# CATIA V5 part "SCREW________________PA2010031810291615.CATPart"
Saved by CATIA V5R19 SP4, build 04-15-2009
Part number: SCREW________________PA2010031810291615
Bounding box of the stored display mesh (mm): x -2.742 to 2.742, y -2.75 to 2.75, z -16 to 2
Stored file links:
  E:\CadInnWork\1\SCREW________________PA2010031810291615.CATPart
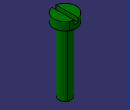
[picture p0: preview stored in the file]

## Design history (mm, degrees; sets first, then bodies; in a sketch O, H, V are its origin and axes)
Parameters
  Update = false
  PDM_version = "A"
  PDM_iteration = 1
  PDM_owner = "moren                    "
  PDM_comment = ""
  PDM_partnumber = "PA002170EA6A57201003181029160015"
Body1 (main body)
  Sketch1 on yz-plane, origin (0, 0, 0), H (0, 1, 0), V (0, 0, 1)
    axis line L1 (0, 73.7857) -> (0, -77.8237)
    point P1 (0, 73.7857)
    point P3 (0, 2)
    line L2 (0, 2) -> (2.75, 2)
    line L3 (2.75, 2) -> (2.75, 0)
    point P5 (2.75, 0)
    line L4 (2.75, 0) -> (1.5, 0)
    line L5 (1.5, 0) -> (1.5, -16)
    line L6 (1.5, -16) -> (0, -16)
    point P8 (0, -16)
    "Radius" L5 L1 = 1.5
    "Radius" L3 L1 = 2.75
    length L3 = 2
    distance L4 L6 = 16
    coincidence: P1 V, P3 L1, P5 H, P8 L1
    vertical: L1 V, L3 V, L5 V
    horizontal: L2 H, L4 H, L6 H
  Shaft1: profile Sketch1, axis Sketch1.L1, angle 360
  Chamfer1: length 0.25, angle 45, on edge [face of Shaft1 from Sketch1.L5 | face of Shaft1 from Sketch1.L6]
  Sketch2 on zx-plane, origin (0, 0, 0), H (-1, 0, 0), V (0, 0, 1)
    line L1 (-0.5, 3.7732) -> (0.5, 3.7732)
    line L2 (0.5, 3.7732) -> (0.5, 1)
    line L3 (0.5, 1) -> (-0.5, 1)
    line L4 (-0.5, 1) -> (-0.5, 3.7732)
    distance L3 H = 1
    length L1 = 1
    horizontal: L1 H, L3 H
    vertical: L2 V, L4 V
    symmetry: L2 L4 V
  Pocket1: profile Sketch2, direction (0, -1, 0), through (limit type 3), opposite side through (limit type 3)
